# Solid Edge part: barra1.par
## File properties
Author: there
Template: iso metric part.par
Last saved by: there
Revision: 3
Application: Solid Edge
Precisión: 0.990
Username: there
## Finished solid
Body 1: solid body, 8 faces, 16 edges, 8 vertices.
  Faces by surface: cylinder 4, plane 4
  Edges by curve: circle 8, line 8
Bounding box of the edges (mm): 12.500 x 3.000 x 52.900, from (-6.25, -3, -46.65) to (6.25, 0, 6.25).
Cylindrical faces by radius (mm): R3.2 x2, R6.25 x2
Planar faces by outward normal: +x 1, +y 1, -x 1, -y 1
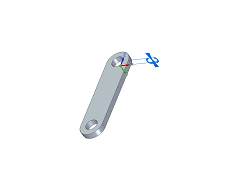
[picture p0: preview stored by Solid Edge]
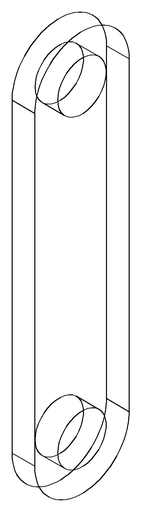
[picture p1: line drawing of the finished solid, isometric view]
